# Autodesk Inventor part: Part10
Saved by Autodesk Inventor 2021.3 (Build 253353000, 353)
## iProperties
Created: 2022-07
Part Number: Part10
Material: Generic
Document SubType Name: Modeling
Designer: Administrator
Density: 1 g/cm^3
Appearance: Default
Author: Administrator
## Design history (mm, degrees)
feature "Drive body"
body "Solid1"
